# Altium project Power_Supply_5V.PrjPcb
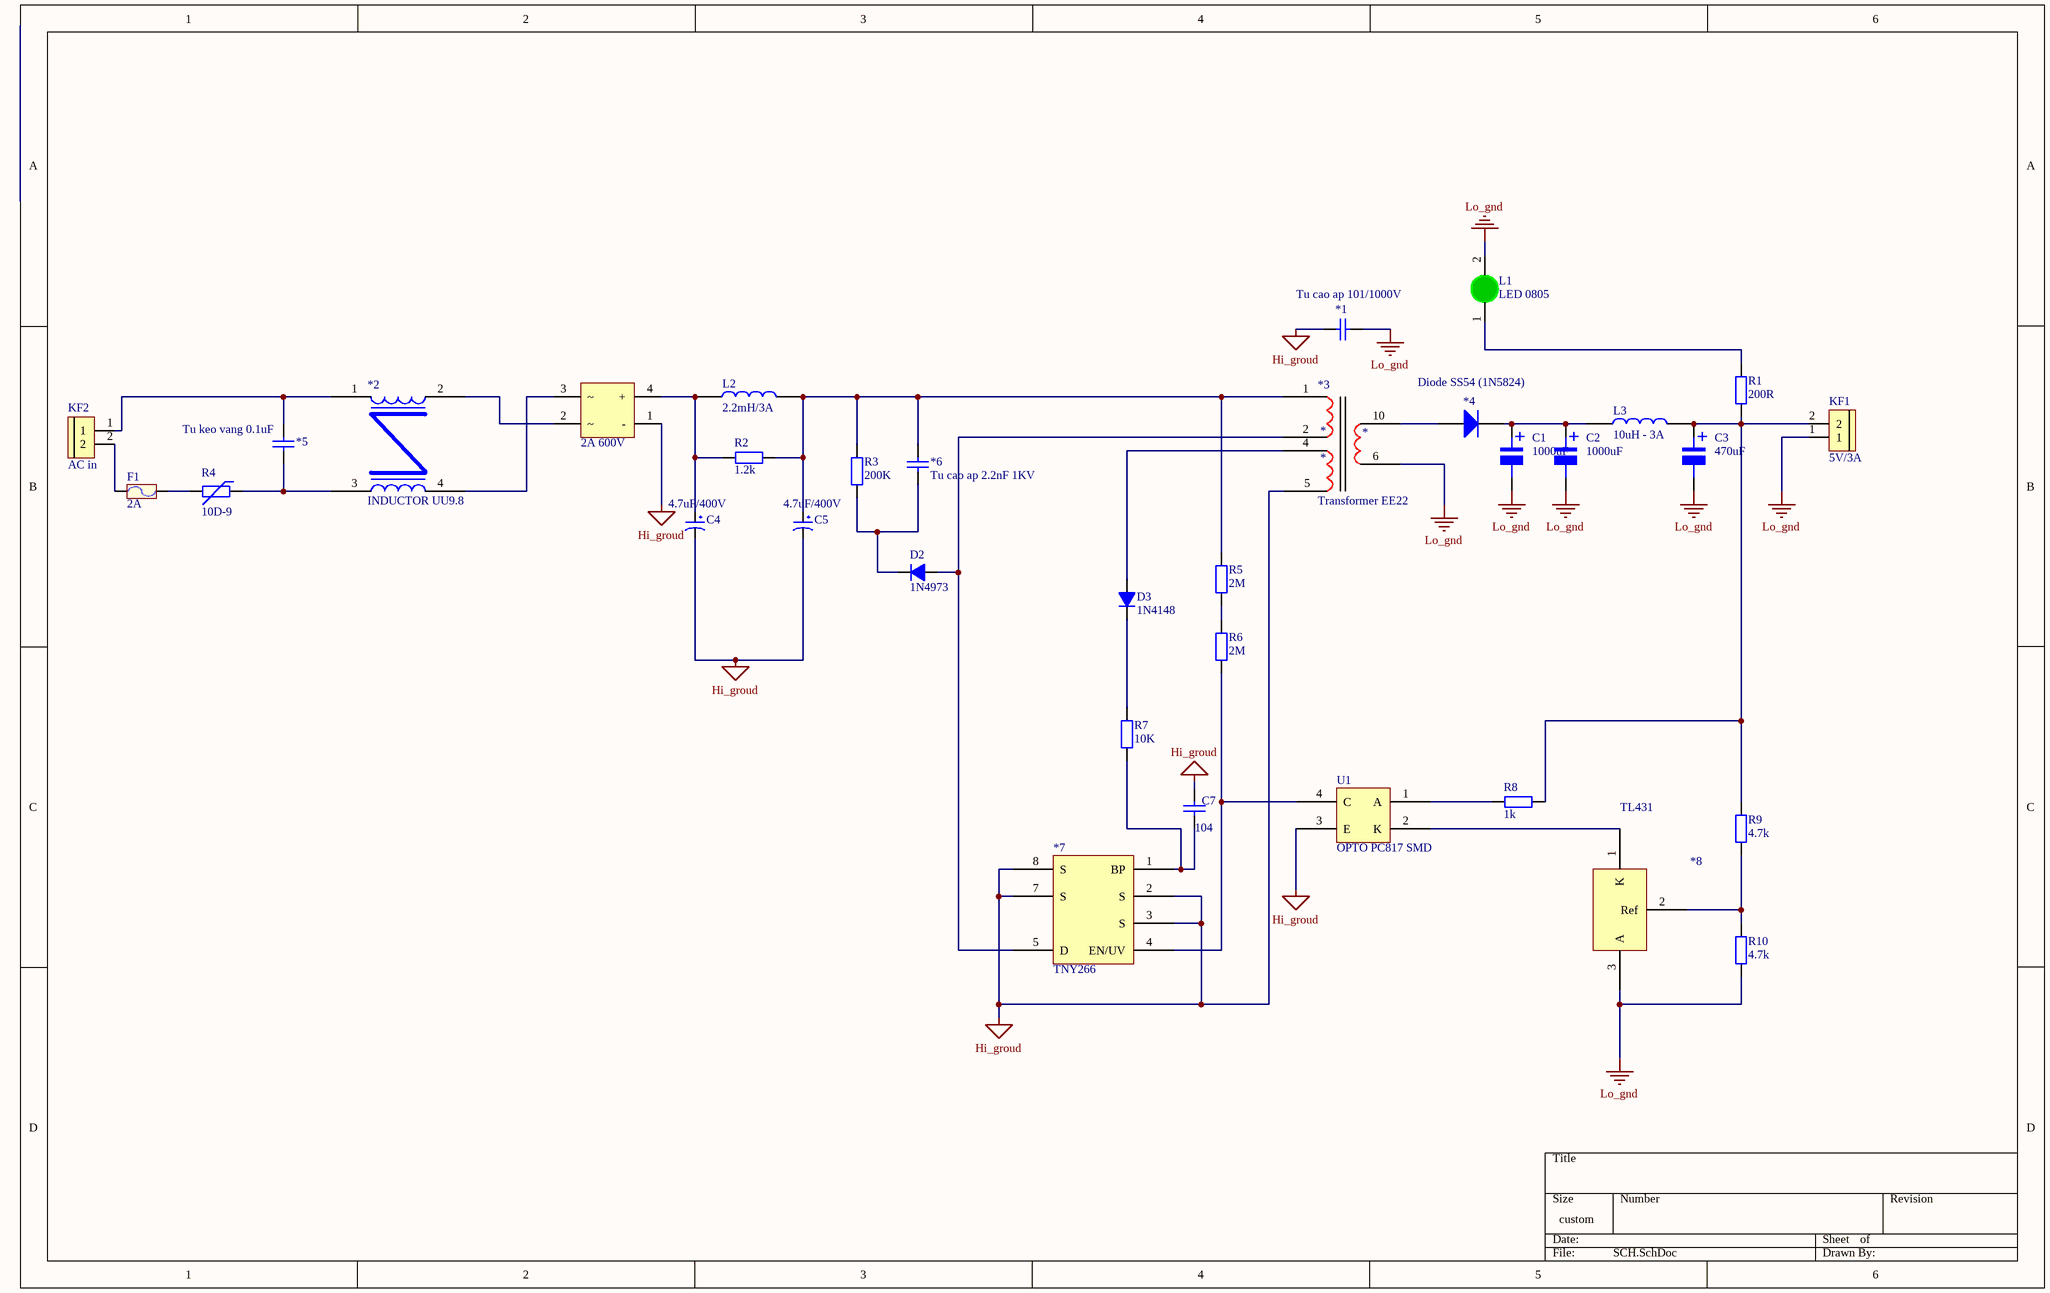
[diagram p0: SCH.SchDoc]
1 sheet, 34 parts. Net scope: global (net labels, ports and power ports of the same name join across sheets).
Board file: PCB.PcbDoc

## Sheet SCH.SchDoc
size 381 x 241 mm; SheetNumber: 1; SheetTotal: 1

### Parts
*1  Tu cao ap 101/1000V  [Tu cao ap]
*2  INDUCTOR UU9.8  [INDUCTOR UU9.8]
*3  Transformer EE22  [TRANSFORMER EE22]
*4  Diode SS54 (1N5824)  [DIODE SMA]
*5  Tu keo vang 0.1uF  [Tu keo vang 0.1uF]
*6  Tu cao ap 2.2nF 1KV  [Tu cao ap]
*7  TNY266  [DIP8]
*8  TL431  [TL431 SOT-23-3]
C1  1000uF  [tu nhom 10 (G)]
C2  1000uF  [tu nhom 10 (G)]
C3  470uF  [tu nhom 8 (f)]
C4  4.7uF/400V  [tu hoa 8mm]
C5  4.7uF/400V  [tu hoa 8mm]
C7  104  [tu 1206]
D1  2A 600V  [DIODE CAU 2A 3A CAM]
D2  1N4973  [DIODE 1A]
D3  1N4148  [DIODE 0.5A]
F1  2A  [De Cau Chi 520 630]
KF1  5V/3A  [Con 2 KF301 5.08]
KF2  AC in  [Con 2 KF301 5.08]
L1  LED 0805  [LED-1206-Green]
L2  2.2mH/3A  [CUON CAM 100uH3A]
L3  10uH - 3A  [CUON CAM 100uH3A]
R1  200R  [tro smd 1206]
R2  1.2k  [tro smd 1206]
R3  200K  [Dien tro]
R4  10D-9  [tro nhiet d-9]
R5  2M  [Dien tro]
R6  2M  [Dien tro]
R7  10K  [Dien tro]
R8  1k  [tro smd 1206]
R9  4.7k  [tro smd 1206]
R10  4.7k  [tro smd 1206]
U1  OPTO PC817 SMD  [SOP4]

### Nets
Hi_groud: *1.2 *3.5 *7.2(S) *7.3(S) *7.7(S) *7.8(S) C4.2 C5.2 C7.1 D1.1(-) U1.3(E)
Lo_gnd: *1.1 *3.6 *8.3(A) C1.2 C2.2 C3.2 KF1.1 L1.2(K) R10.1
Net*2_1: *2.1 *5.1 KF2.1
Net*2_2: *2.2 D1.2
Net*2_3: *2.3 *5.2 R4.1
Net*2_4: *2.4 D1.3
Net*3_1: *3.1 *6.1 C5.1 L2.2 R2.2 R3.2 R5.2
Net*3_2: *3.2 *7.5(D) D2.1(A)
Net*3_4: *3.4 D3.1(A)
Net*3_10: *3.10 *4.1(A)
Net*4_2: *4.2(K) C1.1 C2.1 L3.1
Net*6_2: *6.2 D2.2(K) R3.1
Net*7_1: *7.1(BP) C7.2 R7.1
Net*7_4: *7.4(EN/UV) R6.1 U1.4(C)
Net*8_1: *8.1(K) U1.2(K)
Net*8_2: *8.2(Ref) R9.1 R10.2
NetC3_1: C3.1 KF1.2 L3.2 R1.2 R8.2 R9.2
NetC4_1: C4.1 D1.4(+) L2.1 R2.1
NetD3_2: D3.2(K) R7.2
NetF1_1: F1.1 R4.2
NetF1_2: F1.2 KF2.2
NetL1_1: L1.1(A) R1.1
NetR5_1: R5.1 R6.2
NetR8_1: R8.1 U1.1(A)

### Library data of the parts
*1 = Tu cao ap 1000V
*7 = TNY264
C1 C2 = Tu Nhom 1000uF 10V: Dán; So_Chan: 2; Don_Vi: Con; Ten_Linh_Kien: Tụ Nhôm 1000uF 10V; Ma_Hang: MH007515
C3 = Tu Nhom 470uF 16V: Dán; Don_Vi: Con; So_Chan: 2; Ten_Linh_Kien: Tụ Nhôm 470uF 16V 8x10.4MM; Ma_Hang: MH001940
C4 C5 = Tu Hoa 4.7uF 400V 8x12: Cắm; Don_Vi: Con; So_Chan: 2; Ten_Linh_Kien: Tụ Hóa 4.7uF 400V 8x12MM; Ma_Hang: MH003744
C7 = Tu 1206 104 50V 20%: Dán; Don_Vi: Con; So_Chan: 2; Ten_Linh_Kien: Tụ 1206 104-0.1uF 20% 50V; Ma_Hang: MH004544
D1 = Diode CAU 2A VUONG: Cắm; Ten_Linh_Kien: Diode Cầu 2A 600V KBP206 Vuông; Don_Vi: Con; Ma_Hang: MH001206
D2 = Diode 1N4007: Cắm; Ten_Linh_Kien: Diode 1N4007 1A (DIP); Don_Vi: Con; Ma_Hang: MH001063
D3 = Diode 1N4148: Cắm; Ten_Linh_Kien: Diode 1N4148 DO35 450mA 100V ( 1N4148 DIP); Don_Vi: Con; Ma_Hang: MH001065
F1 = De Cau Chi 520 630: 5x20mm; Ma_Hang: MH001473; Ten: Đế Cầu Chì 5x20MM 6x30MM SMD01
KF1 KF2 = CON 2 KF301: Cắm; Ma_Hang: MH000987; Ten_Linh_Kien: CON 2 KF301-2P 5.08MM Xanh Dương; Don_Vi: Con
L1 = LED 1206 Xanh La: Dán; Don_Vi: Con; Ma_Hang: MH002947; Ten_Linh_Kien: LED1206 Màu Xanh Lá (Green)
L2 L3 = CUON CAM 470uH DIP: Cắm; Don_Vi: Con; Ma_Hang: MH002232; Ten_Linh_Kien: Cuộn Cảm 470uH 3A 8x10MM
R1 = Tro 1206 1% 200R: Dán; So_Chan: 2; Don_Vi: Con; Ten_Linh_Kien: Trở 1206 1% 200R; Ma_Hang: MH005895
R2 R8 = Tro 1206 1% 1k: Dán; Don_Vi: Con; So_Chan: 2; Ten_Linh_Kien: Trở 1206 1% 1k; Ma_Hang: MH005880
R3 R5-R7 = Resistor: Cắm
R4 = Tro Nhiet NTC 10D-9: Cắm; So_Chan: 2; Don_Vi: Con; Ten_Linh_Kien: Điện trở nhiệt NTC 10D-9; Ma_Hang: MH000922
R9 R10 = Tro 1206 5% 4.7K: Dán; So_Chan: 2; Don_Vi: Con; Ten_Linh_Kien: Trở 1206 5% 4.7k; Ma_Hang: MH005908
U1 = OPTO PC817 SMD: Single Opto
